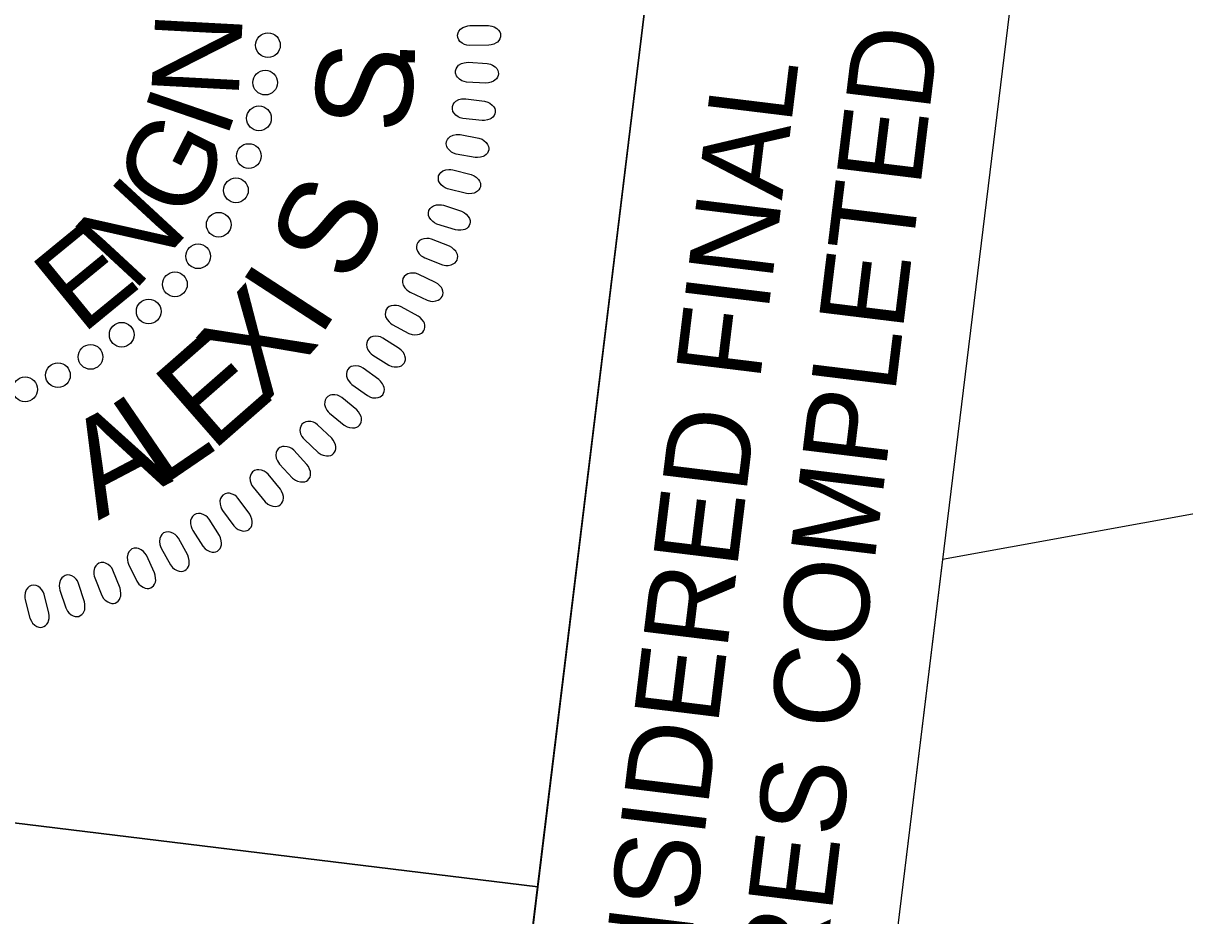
# Model space of a CAD drawing. Extents: x 480344 to 482186, y 489602 to 491961.
# Drawn here: x 481131.1 to 481206.4, y 491821.7 to 491879.5 of the extents above; entities that cross this region are included whole.
import ezdxf

# ---------------------------------------------------------------- set-up
doc = ezdxf.new("R2010")
doc.units = 0
for name, color, linetype in [('Matchline', 7, 'Continuous'), ('Sheet Layout Plan Border', 7, 'Continuous'), ('Sheet PE Seal Cell', 7, 'Continuous'), ('Sheet Plan CELL', 7, 'Continuous'), ('Sheet Sticker Exception Certification CELL', 7, 'Continuous')]:
    doc.layers.add(name, color=color, linetype=linetype)

msp = doc.modelspace()

# ---------------------------------------------------------------- linework, layer by layer
at = {"layer": 'Matchline'}
msp.add_line((481441.949, 491890.415), (481190.711, 491844.783), dxfattribs=at)
at = {"layer": 'Sheet Layout Plan Border'}
for points in [[(481091.905, 490519.697), (481587.497, 490459.166), (481698.337, 490347.937), (481789.232, 490336.837), (481888.023, 490324.774), (481894.085, 490374.405), (482045.289, 491612.381), (481950.415, 491623.251), (481975.379, 491825.264), (481441.949, 491890.415), (481190.711, 491844.783), (481175.643, 491721.417), (481003.373, 491742.458), (480851.83, 490501.703)], [(481091.905, 490519.697), (481587.497, 490459.166), (481698.337, 490347.937), (481789.232, 490336.837), (481888.023, 490324.774), (481894.085, 490374.405), (482045.289, 491612.381), (481950.415, 491623.251), (481955.434, 491661.965), (481633.659, 491701.266), (481441.949, 491890.415), (481190.711, 491844.783), (481175.643, 491721.417), (481003.373, 491742.458), (480851.83, 490501.703)]]:
    msp.add_lwpolyline(points, close=True, dxfattribs=at)
at = {"layer": 'Sheet PE Seal Cell'}
for points in [[(481160.052, 491879.392), (481161.279, 491879.396), (481161.498, 491879.36), (481161.638, 491879.308), (481161.809, 491879.197), (481161.918, 491879.1), (481161.999, 491878.988), (481162.039, 491878.884), (481162.059, 491878.771), (481162.039, 491878.66), (481162.01, 491878.539), (481161.951, 491878.435), (481161.851, 491878.33), (481161.772, 491878.269), (481161.622, 491878.201), (481161.443, 491878.141), (481161.284, 491878.118), (481160.027, 491878.106), (481159.858, 491878.128), (481159.718, 491878.172), (481159.558, 491878.261), (481159.418, 491878.372), (481159.337, 491878.47), (481159.277, 491878.626), (481159.257, 491878.776), (481159.296, 491878.925), (481159.346, 491879.03), (481159.445, 491879.158), (481159.613, 491879.277), (481159.794, 491879.346), (481159.922, 491879.376)], [(481159.958, 491877.02), (481161.183, 491876.947), (481161.399, 491876.897), (481161.536, 491876.837), (481161.698, 491876.715), (481161.802, 491876.612), (481161.875, 491876.495), (481161.908, 491876.388), (481161.922, 491876.275), (481161.895, 491876.165), (481161.858, 491876.047), (481161.793, 491875.946), (481161.686, 491875.847), (481161.604, 491875.792), (481161.45, 491875.734), (481161.267, 491875.685), (481161.107, 491875.672), (481159.852, 491875.738), (481159.684, 491875.771), (481159.547, 491875.824), (481159.394, 491875.923), (481159.26, 491876.043), (481159.187, 491876.145), (481159.136, 491876.305), (481159.125, 491876.456), (481159.174, 491876.602), (481159.23, 491876.704), (481159.336, 491876.825), (481159.513, 491876.934), (481159.697, 491876.991), (481159.827, 491877.013)], [(481159.792, 491874.656), (481161.01, 491874.506), (481161.223, 491874.442), (481161.356, 491874.374), (481161.51, 491874.242), (481161.607, 491874.132), (481161.673, 491874.01), (481161.7, 491873.903), (481161.705, 491873.788), (481161.672, 491873.68), (481161.628, 491873.564), (481161.557, 491873.468), (481161.444, 491873.376), (481161.358, 491873.326), (481161.201, 491873.278), (481161.016, 491873.24), (481160.855, 491873.237), (481159.607, 491873.383), (481159.441, 491873.426), (481159.308, 491873.487), (481159.16, 491873.595), (481159.035, 491873.724), (481158.968, 491873.83), (481158.928, 491873.993), (481158.926, 491874.144), (481158.984, 491874.288), (481159.046, 491874.386), (481159.16, 491874.5), (481159.343, 491874.597), (481159.53, 491874.643), (481159.662, 491874.656)], [(481159.436, 491872.328), (481160.642, 491872.103), (481160.85, 491872.026), (481160.978, 491871.949), (481161.124, 491871.807), (481161.215, 491871.692), (481161.272, 491871.567), (481161.292, 491871.457), (481161.291, 491871.342), (481161.25, 491871.237), (481161.2, 491871.125), (481161.122, 491871.033), (481161.004, 491870.948), (481160.915, 491870.903), (481160.755, 491870.865), (481160.568, 491870.839), (481160.407, 491870.846), (481159.17, 491871.07), (481159.008, 491871.123), (481158.879, 491871.193), (481158.739, 491871.311), (481158.621, 491871.446), (481158.561, 491871.557), (481158.531, 491871.722), (481158.539, 491871.872), (481158.606, 491872.012), (481158.674, 491872.105), (481158.795, 491872.212), (481158.984, 491872.298), (481159.173, 491872.332), (481159.305, 491872.337)], [(481158.959, 491870.052), (481160.148, 491869.751), (481160.351, 491869.661), (481160.474, 491869.576), (481160.612, 491869.426), (481160.694, 491869.305), (481160.744, 491869.177), (481160.757, 491869.066), (481160.748, 491868.952), (481160.702, 491868.849), (481160.643, 491868.739), (481160.56, 491868.653), (481160.437, 491868.576), (481160.345, 491868.537), (481160.183, 491868.509), (481159.995, 491868.495), (481159.835, 491868.512), (481158.615, 491868.812), (481158.456, 491868.876), (481158.332, 491868.954), (481158.199, 491869.08), (481158.091, 491869.223), (481158.038, 491869.337), (481158.018, 491869.503), (481158.035, 491869.653), (481158.111, 491869.788), (481158.185, 491869.878), (481158.312, 491869.977), (481158.506, 491870.05), (481158.697, 491870.072), (481158.83, 491870.069)], [(481158.348, 491867.743), (481159.517, 491867.368), (481159.714, 491867.266), (481159.831, 491867.173), (481159.958, 491867.015), (481160.033, 491866.889), (481160.075, 491866.757), (481160.081, 491866.646), (481160.065, 491866.533), (481160.012, 491866.433), (481159.947, 491866.327), (481159.858, 491866.246), (481159.731, 491866.177), (481159.637, 491866.144), (481159.474, 491866.126), (481159.285, 491866.124), (481159.126, 491866.151), (481157.927, 491866.528), (481157.772, 491866.601), (481157.653, 491866.687), (481157.529, 491866.82), (481157.43, 491866.97), (481157.383, 491867.087), (481157.375, 491867.254), (481157.402, 491867.403), (481157.485, 491867.533), (481157.565, 491867.618), (481157.698, 491867.708), (481157.896, 491867.77), (481158.088, 491867.78), (481158.22, 491867.768)], [(481157.139, 491864.343), (481158.282, 491863.895), (481158.499, 491863.85), (481158.648, 491863.847), (481158.848, 491863.89), (481158.985, 491863.94), (481159.1, 491864.016), (481159.176, 491864.099), (481159.235, 491864.196), (481159.257, 491864.308), (481159.272, 491864.43), (481159.256, 491864.549), (481159.201, 491864.683), (481159.149, 491864.768), (481159.033, 491864.885), (481158.888, 491865.006), (481158.747, 491865.085), (481157.58, 491865.551), (481157.414, 491865.591), (481157.268, 491865.6), (481157.086, 491865.575), (481156.916, 491865.522), (481156.806, 491865.46), (481156.693, 491865.335), (481156.62, 491865.204), (481156.602, 491865.049), (481156.611, 491864.934), (481156.657, 491864.779), (481156.772, 491864.607), (481156.915, 491864.478), (481157.024, 491864.404)], [(481156.188, 491862.108), (481157.3, 491861.59), (481157.515, 491861.531), (481157.664, 491861.519), (481157.865, 491861.55), (481158.005, 491861.591), (481158.125, 491861.66), (481158.205, 491861.737), (481158.271, 491861.831), (481158.3, 491861.941), (481158.323, 491862.062), (481158.314, 491862.182), (481158.267, 491862.319), (481158.22, 491862.407), (481158.113, 491862.531), (481157.975, 491862.661), (481157.841, 491862.749), (481156.705, 491863.287), (481156.541, 491863.338), (481156.396, 491863.355), (481156.213, 491863.342), (481156.04, 491863.299), (481155.926, 491863.245), (481155.805, 491863.128), (481155.724, 491863.001), (481155.697, 491862.848), (481155.699, 491862.732), (481155.735, 491862.575), (481155.838, 491862.396), (481155.973, 491862.258), (481156.078, 491862.177)], [(481155.025, 491860.025), (481156.103, 491859.438), (481156.313, 491859.366), (481156.461, 491859.345), (481156.664, 491859.362), (481156.806, 491859.395), (481156.93, 491859.456), (481157.015, 491859.528), (481157.086, 491859.618), (481157.122, 491859.725), (481157.153, 491859.845), (481157.151, 491859.965), (481157.113, 491860.105), (481157.072, 491860.196), (481156.973, 491860.326), (481156.844, 491860.465), (481156.714, 491860.561), (481155.614, 491861.168), (481155.455, 491861.23), (481155.311, 491861.257), (481155.128, 491861.255), (481154.952, 491861.223), (481154.835, 491861.176), (481154.707, 491861.067), (481154.618, 491860.945), (481154.582, 491860.795), (481154.576, 491860.679), (481154.602, 491860.52), (481154.694, 491860.333), (481154.82, 491860.188), (481154.919, 491860.1)], [(481153.767, 491858.036), (481154.805, 491857.383), (481155.01, 491857.297), (481155.156, 491857.267), (481155.36, 491857.271), (481155.504, 491857.295), (481155.631, 491857.348), (481155.721, 491857.415), (481155.798, 491857.5), (481155.84, 491857.605), (481155.879, 491857.722), (481155.884, 491857.842), (481155.855, 491857.984), (481155.82, 491858.078), (481155.729, 491858.214), (481155.609, 491858.361), (481155.486, 491858.465), (481154.426, 491859.14), (481154.27, 491859.211), (481154.128, 491859.247), (481153.946, 491859.257), (481153.768, 491859.236), (481153.648, 491859.196), (481153.514, 491859.095), (481153.417, 491858.979), (481153.372, 491858.832), (481153.358, 491858.716), (481153.375, 491858.556), (481153.455, 491858.365), (481153.571, 491858.212), (481153.665, 491858.118)], [(481152.419, 491856.125), (481153.414, 491855.408), (481153.614, 491855.311), (481153.757, 491855.271), (481153.96, 491855.263), (481154.107, 491855.277), (481154.237, 491855.322), (481154.33, 491855.383), (481154.412, 491855.463), (481154.461, 491855.565), (481154.507, 491855.68), (481154.52, 491855.8), (481154.5, 491855.943), (481154.47, 491856.038), (481154.388, 491856.18), (481154.277, 491856.334), (481154.161, 491856.445), (481153.146, 491857.186), (481152.996, 491857.266), (481152.855, 491857.312), (481152.674, 491857.333), (481152.495, 491857.324), (481152.374, 491857.291), (481152.233, 491857.199), (481152.13, 491857.089), (481152.075, 491856.945), (481152.054, 491856.83), (481152.06, 491856.669), (481152.129, 491856.473), (481152.234, 491856.313), (481152.322, 491856.213)], [(481150.967, 491854.27), (481151.916, 491853.492), (481152.109, 491853.381), (481152.25, 491853.333), (481152.452, 491853.312), (481152.598, 491853.318), (481152.731, 491853.354), (481152.829, 491853.409), (481152.915, 491853.483), (481152.971, 491853.582), (481153.024, 491853.694), (481153.044, 491853.813), (481153.033, 491853.957), (481153.009, 491854.054), (481152.937, 491854.201), (481152.836, 491854.361), (481152.727, 491854.479), (481151.76, 491855.282), (481151.615, 491855.372), (481151.478, 491855.426), (481151.298, 491855.458), (481151.119, 491855.461), (481150.996, 491855.435), (481150.85, 491855.353), (481150.74, 491855.249), (481150.676, 491855.108), (481150.648, 491854.996), (481150.644, 491854.835), (481150.699, 491854.635), (481150.796, 491854.469), (481150.876, 491854.363)], [(481149.334, 491852.553), (481150.232, 491851.717), (481150.418, 491851.595), (481150.555, 491851.538), (481150.756, 491851.504), (481150.903, 491851.501), (481151.038, 491851.529), (481151.138, 491851.578), (481151.229, 491851.646), (481151.291, 491851.742), (481151.35, 491851.85), (481151.378, 491851.967), (481151.376, 491852.112), (481151.359, 491852.21), (481151.295, 491852.361), (481151.204, 491852.527), (481151.103, 491852.652), (481150.189, 491853.514), (481150.05, 491853.614), (481149.917, 491853.676), (481149.739, 491853.719), (481149.56, 491853.733), (481149.436, 491853.716), (481149.285, 491853.642), (481149.168, 491853.546), (481149.096, 491853.409), (481149.061, 491853.298), (481149.047, 491853.138), (481149.09, 491852.935), (481149.175, 491852.763), (481149.25, 491852.653)], [(481147.728, 491850.956), (481148.571, 491850.064), (481148.749, 491849.931), (481148.883, 491849.865), (481149.081, 491849.819), (481149.227, 491849.807), (481149.363, 491849.825), (481149.467, 491849.868), (481149.563, 491849.931), (481149.629, 491850.022), (481149.696, 491850.126), (481149.731, 491850.241), (481149.738, 491850.386), (481149.727, 491850.485), (481149.673, 491850.64), (481149.593, 491850.811), (481149.5, 491850.943), (481148.641, 491851.861), (481148.509, 491851.969), (481148.379, 491852.039), (481148.205, 491852.093), (481148.028, 491852.118), (481147.902, 491852.109), (481147.747, 491852.044), (481147.625, 491851.956), (481147.544, 491851.824), (481147.502, 491851.716), (481147.478, 491851.556), (481147.508, 491851.351), (481147.582, 491851.174), (481147.65, 491851.06)], [(481146.004, 491849.464), (481146.79, 491848.521), (481146.959, 491848.377), (481147.088, 491848.303), (481147.283, 491848.244), (481147.429, 491848.222), (481147.565, 491848.233), (481147.671, 491848.269), (481147.77, 491848.326), (481147.843, 491848.413), (481147.916, 491848.513), (481147.958, 491848.625), (481147.974, 491848.769), (481147.97, 491848.868), (481147.926, 491849.027), (481147.856, 491849.203), (481147.772, 491849.34), (481146.972, 491850.31), (481146.847, 491850.425), (481146.722, 491850.504), (481146.552, 491850.569), (481146.377, 491850.605), (481146.251, 491850.604), (481146.092, 491850.549), (481145.964, 491850.468), (481145.875, 491850.342), (481145.827, 491850.237), (481145.792, 491850.079), (481145.809, 491849.872), (481145.873, 491849.691), (481145.933, 491849.572)], [(481144.029, 491847.957), (481144.754, 491846.967), (481144.913, 491846.812), (481145.038, 491846.73), (481145.228, 491846.659), (481145.372, 491846.629), (481145.509, 491846.63), (481145.618, 491846.66), (481145.72, 491846.71), (481145.798, 491846.793), (481145.877, 491846.888), (481145.926, 491846.997), (481145.951, 491847.14), (481145.953, 491847.239), (481145.919, 491847.4), (481145.861, 491847.58), (481145.785, 491847.722), (481145.048, 491848.74), (481144.93, 491848.864), (481144.811, 491848.95), (481144.645, 491849.026), (481144.472, 491849.072), (481144.346, 491849.079), (481144.184, 491849.035), (481144.052, 491848.962), (481143.955, 491848.842), (481143.9, 491848.739), (481143.856, 491848.584), (481143.86, 491848.377), (481143.912, 491848.192), (481143.964, 491848.07)], [(481142.088, 491846.672), (481142.75, 491845.639), (481142.899, 491845.475), (481143.018, 491845.385), (481143.204, 491845.302), (481143.345, 491845.262), (481143.482, 491845.256), (481143.592, 491845.278), (481143.697, 491845.322), (481143.781, 491845.399), (481143.865, 491845.489), (481143.922, 491845.596), (481143.955, 491845.736), (481143.963, 491845.836), (481143.939, 491845.998), (481143.893, 491846.181), (481143.826, 491846.328), (481143.155, 491847.391), (481143.045, 491847.521), (481142.931, 491847.614), (481142.77, 491847.7), (481142.6, 491847.758), (481142.475, 491847.773), (481142.311, 491847.739), (481142.174, 491847.674), (481142.07, 491847.56), (481142.009, 491847.462), (481141.955, 491847.309), (481141.945, 491847.102), (481141.986, 491846.914), (481142.031, 491846.789)], [(481140.05, 491845.507), (481140.646, 491844.434), (481140.785, 491844.261), (481140.898, 491844.163), (481141.078, 491844.07), (481141.217, 491844.021), (481141.353, 491844.006), (481141.464, 491844.022), (481141.572, 491844.059), (481141.66, 491844.13), (481141.75, 491844.215), (481141.813, 491844.318), (481141.856, 491844.456), (481141.869, 491844.555), (481141.856, 491844.718), (481141.821, 491844.904), (481141.764, 491845.054), (481141.16, 491846.157), (481141.058, 491846.294), (481140.951, 491846.394), (481140.796, 491846.49), (481140.63, 491846.558), (481140.506, 491846.581), (481140.34, 491846.557), (481140.199, 491846.502), (481140.088, 491846.394), (481140.021, 491846.3), (481139.957, 491846.151), (481139.936, 491845.945), (481139.964, 491845.755), (481140, 491845.628)], [(481137.935, 491844.48), (481138.462, 491843.371), (481138.589, 491843.189), (481138.696, 491843.086), (481138.871, 491842.98), (481139.005, 491842.923), (481139.141, 491842.899), (481139.253, 491842.908), (481139.363, 491842.938), (481139.455, 491843.005), (481139.55, 491843.083), (481139.619, 491843.182), (481139.671, 491843.317), (481139.691, 491843.414), (481139.687, 491843.579), (481139.664, 491843.766), (481139.616, 491843.92), (481139.084, 491845.058), (481138.991, 491845.202), (481138.889, 491845.309), (481138.741, 491845.414), (481138.579, 491845.492), (481138.457, 491845.523), (481138.29, 491845.509), (481138.146, 491845.463), (481138.028, 491845.363), (481137.956, 491845.273), (481137.883, 491845.128), (481137.848, 491844.924), (481137.864, 491844.732), (481137.893, 491844.603)], [(481135.736, 491843.583), (481136.192, 491842.444), (481136.308, 491842.255), (481136.408, 491842.144), (481136.575, 491842.028), (481136.707, 491841.963), (481136.84, 491841.931), (481136.952, 491841.932), (481137.064, 491841.956), (481137.16, 491842.016), (481137.26, 491842.089), (481137.335, 491842.182), (481137.395, 491842.314), (481137.421, 491842.41), (481137.428, 491842.574), (481137.416, 491842.763), (481137.379, 491842.92), (481136.918, 491844.089), (481136.834, 491844.238), (481136.74, 491844.351), (481136.598, 491844.465), (481136.442, 491844.553), (481136.322, 491844.592), (481136.154, 491844.589), (481136.008, 491844.551), (481135.884, 491844.459), (481135.805, 491844.374), (481135.724, 491844.234), (481135.677, 491844.032), (481135.681, 491843.84), (481135.701, 491843.709)], [(481131.223, 491842.173), (481131.533, 491840.986), (481131.625, 491840.783), (481131.71, 491840.661), (481131.861, 491840.525), (481131.983, 491840.443), (481132.112, 491840.395), (481132.223, 491840.383), (481132.337, 491840.391), (481132.44, 491840.439), (481132.548, 491840.498), (481132.634, 491840.582), (481132.71, 491840.705), (481132.748, 491840.798), (481132.775, 491840.96), (481132.788, 491841.148), (481132.769, 491841.308), (481132.46, 491842.526), (481132.395, 491842.685), (481132.316, 491842.808), (481132.19, 491842.94), (481132.046, 491843.047), (481131.932, 491843.1), (481131.764, 491843.118), (481131.614, 491843.099), (481131.481, 491843.023), (481131.392, 491842.948), (481131.293, 491842.82), (481131.222, 491842.626), (481131.201, 491842.435), (481131.205, 491842.302)], [(481133.476, 491842.804), (481133.859, 491841.639), (481133.963, 491841.442), (481134.057, 491841.326), (481134.217, 491841.2), (481134.343, 491841.126), (481134.475, 491841.085), (481134.586, 491841.08), (481134.699, 491841.096), (481134.799, 491841.15), (481134.904, 491841.217), (481134.984, 491841.306), (481135.052, 491841.433), (481135.084, 491841.527), (481135.101, 491841.691), (481135.102, 491841.88), (481135.073, 491842.038), (481134.688, 491843.235), (481134.613, 491843.389), (481134.527, 491843.507), (481134.392, 491843.63), (481134.242, 491843.729), (481134.125, 491843.774), (481133.957, 491843.782), (481133.808, 491843.754), (481133.679, 491843.669), (481133.595, 491843.589), (481133.505, 491843.455), (481133.446, 491843.256), (481133.437, 491843.064), (481133.449, 491842.932)]]:
    msp.add_lwpolyline(points, close=True, dxfattribs=at)
for centre in [(481146.968, 491878.126), (481146.791, 491875.701), (481146.387, 491873.384), (481145.726, 491870.938), (481144.892, 491868.714), (481143.776, 491866.484), (481142.442, 491864.441), (481140.935, 491862.62), (481139.235, 491860.863), (481137.484, 491859.353), (481135.462, 491857.916), (481133.35, 491856.73), (481131.22, 491855.813)]:
    msp.add_circle(centre, 0.801, dxfattribs=at)
at = {"layer": 'Sheet Plan CELL'}
for p, q in [((481176.581, 491922.827), (481164.469, 491823.563)), ((481052.787, 491837.204), (481164.421, 491823.582)), ((481164.469, 491823.563), (481052.787, 491837.204))]:
    msp.add_line(p, q, dxfattribs=at)
for points in [[(481888.023, 490324.774), (480845.79, 490452.044), (481003.359, 491742.447), (481152.316, 491724.266), (481176.581, 491922.827), (482069.88, 491813.721)], [(481040.657, 491737.892), (481052.787, 491837.204), (481164.469, 491823.563), (481152.316, 491724.266)]]:
    msp.add_lwpolyline(points, close=True, dxfattribs=at)
at = {"layer": 'Sheet Sticker Exception Certification CELL'}
for p, q in [((481152.316, 491724.266), (481176.568, 491922.828)), ((481152.316, 491724.266), (481176.568, 491922.828)), ((481199.895, 491919.979), (481175.643, 491721.417)), ((481199.895, 491919.979), (481175.643, 491721.417))]:
    msp.add_line(p, q, dxfattribs=at)

# ---------------------------------------------------------------- texts
at = {"layer": 'Sheet PE Seal Cell'}
for s, height, rotation, p in [('N', 5.669, 86.94089, (481145.054, 491874.608)), ('S', 6.236, 82.41913, (481155.945, 491872.238)), ('.', 6.236, 89.26478, (481156.483, 491876.241)), ('I', 5.669, 71.06129, (481144.251, 491871.932)), ('G', 5.669, 63.12149, (481141.892, 491866.55)), ('N', 5.669, 47.2419, (481138.223, 491862.068)), ('S', 6.236, 63.82393, (481152.412, 491862.473)), ('E', 5.669, 39.3021, (481134.91, 491859.314)), ('I', 6.236, 56.97827, (481150.287, 491859.05)), ('X', 6.236, 48.03095, (481146.674, 491854.707)), ('E', 6.236, 41.18529, (481143.311, 491851.691)), ('L', 6.236, 34.33964, (481139.923, 491849.371)), ('A', 6.236, 27.71996, (481135.962, 491847.296))]:
    msp.add_text(s, height=height, rotation=rotation, dxfattribs=at).set_placement(p)
at = {"layer": 'Sheet Sticker Exception Certification CELL'}
for s, p in [('UNLESS ALL SIGNATURES COMPLETED', (481173.26, 491737.827)), ('UNLESS ALL SIGNATURES COMPLETED', (481173.26, 491737.827)), ('DOCUMENT NOT CONSIDERED FINAL', (481165.14, 491743.928)), ('DOCUMENT NOT CONSIDERED FINAL', (481165.14, 491743.928))]:
    msp.add_text(s, height=5.5, rotation=83.03651, dxfattribs=at).set_placement(p)

doc.saveas('drawing.dxf')
